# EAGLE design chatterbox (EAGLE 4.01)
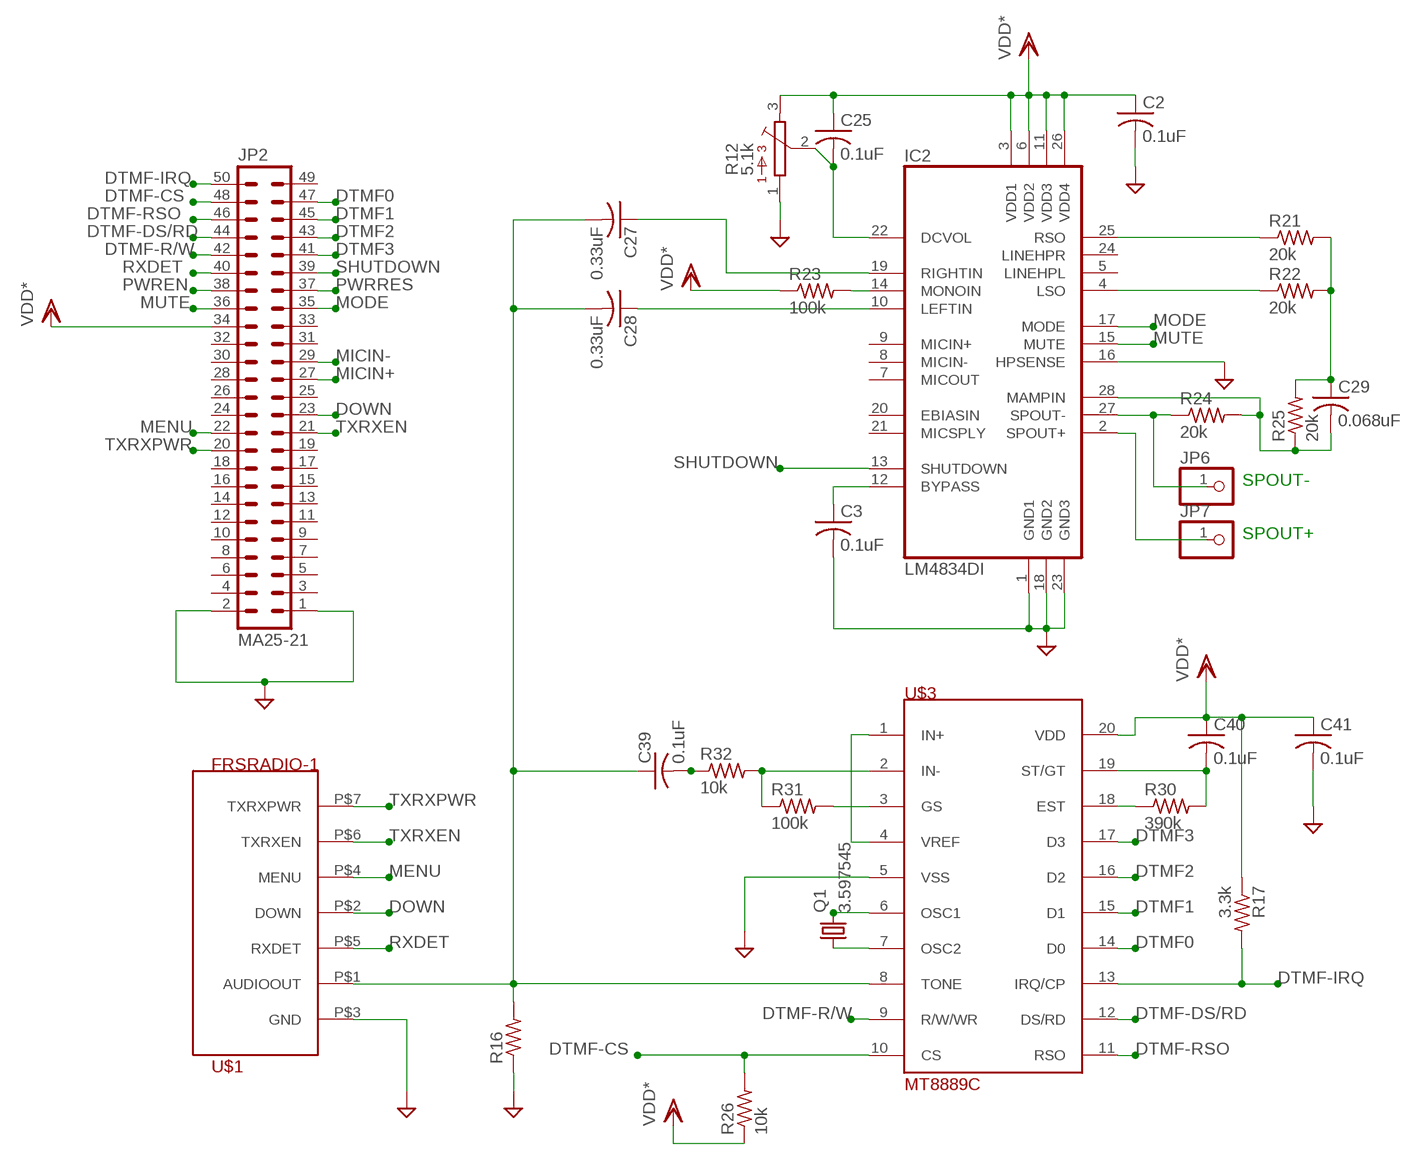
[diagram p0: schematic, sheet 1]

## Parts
C2  0.1uF  C-US050-024X044  [C050-024X044]
C3  0.1uF  C-US050-024X044  [C050-024X044]
C25  0.1uF  C-US050-024X044  [C050-024X044]
C27  0.33uF  C-US050-024X044  [C050-024X044]
C28  0.33uF  C-US050-024X044  [C050-024X044]
C29  0.068uF  C-US050-024X044  [C050-024X044]
C39  0.1uF  C-US050-024X044  [C050-024X044]
C40  0.1uF  C-US050-024X044  [C050-024X044]
C41  0.1uF  C-US050-024X044  [C050-024X044]
IC2  LM4834DI  [DIL28-3]
JP2  MA25-21  [MA25-2]
JP6  PINHD-1X1  [1X01]
JP7  PINHD-1X1  [1X01]
Q1  3.597545  HC49U-V  [HC49U-V]
R12  5.1k  B25U  [B25U]
R16  R-US_0207/10  [0207/10]
R17  3.3k  R-US_0207/10  [0207/10]
R21  20k  R-US_0207/10  [0207/10]
R22  20k  R-US_0207/10  [0207/10]
R23  100k  R-US_0207/10  [0207/10]
R24  20k  R-US_0207/10  [0207/10]
R25  20k  R-US_0207/10  [0207/10]
R26  10k  R-US_0207/10  [0207/10]
R30  390k  R-US_0207/10  [0207/10]
R31  100k  R-US_0207/10  [0207/10]
R32  10k  R-US_0207/10  [0207/10]
U$1  FRSRADIO-1  [FRSRADIO]
U$3  MT8889C  [DIL20]

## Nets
AUDIOIN: C27.2 C39.1 R16.2 U$1.P$1(AUDIOOUT) U$3.8(TONE)
DOWN: JP2.23 U$1.P$2(DOWN)
DTMF0: JP2.47 U$3.14(D0)
DTMF1: JP2.45 U$3.15(D1)
DTMF2: JP2.43 U$3.16(D2)
DTMF3: JP2.41 U$3.17(D3)
DTMF-CS: JP2.48 R26.2 U$3.10(CS)
DTMF-DS/RD: JP2.44 U$3.12(DS/RD)
DTMF-IRQ: JP2.50 R17.2 U$3.13(IRQ/CP)
DTMF-R/W: JP2.42 U$3.9(R/W/WR)
DTMF-RSO: JP2.46 U$3.11(RSO)
GND: C2.2 C3.2 C41.2 IC2.1(GND1) IC2.16(HPSENSE) IC2.18(GND2) IC2.23(GND3) JP2.1 JP2.2 R12.1 R16.1 U$1.P$3(GND) U$3.5(VSS)
MENU: JP2.22 U$1.P$4(MENU)
MICIN+: JP2.27
MICIN-: JP2.29
MODE: IC2.17(MODE) JP2.35
MUTE: IC2.15(MUTE) JP2.36
N$1: C28.2
N$6: IC2.27(SPOUT-) JP6.1 R24.1
N$9: IC2.2(SPOUT+) JP7.1
N$14: C29.2 IC2.28(MAMPIN) R24.2 R25.1
N$18: C3.1 IC2.12(BYPASS)
N$20: C25.2 IC2.22(DCVOL) R12.2
N$29: U$3.1(IN+) U$3.4(VREF)
N$30: R30.1 U$3.18(EST)
N$32: Q1.1 U$3.7(OSC2)
N$33: R31.2 U$3.3(GS)
N$36: C39.2 R32.1
N$37: IC2.14(MONOIN) R23.2
N$38: R31.1 R32.2 U$3.2(IN-)
N$41: C40.2 R30.2 U$3.19(ST/GT)
N$42: IC2.25(RSO) R21.1
N$44: Q1.2 U$3.6(OSC1)
N$45: IC2.4(LSO) R22.1
N$46: C29.1 R21.2 R22.2 R25.2
N$51: C27.1 IC2.19(RIGHTIN)
N$54: C28.1 IC2.10(LEFTIN)
PWREN: JP2.38
PWRRES: JP2.37
RXDET: JP2.40 U$1.P$5(RXDET)
SHUTDOWN: IC2.13(SHUTDOWN) JP2.39
TXRXEN: JP2.21 U$1.P$6(TXRXEN)
TXRXPWR: JP2.20 U$1.P$7(TXRXPWR)
VDD: C2.1 C25.1 C40.1 C41.1 IC2.3(VDD1) IC2.6(VDD2) IC2.11(VDD3) IC2.26(VDD4) JP2.34 R12.3 R17.1 R23.1 R26.1 U$3.20(VDD) ; supply symbol labelled VDD*
Unconnected: IC2.5(LINEHPL) IC2.7(MICOUT) IC2.8(MICIN-) IC2.9(MICIN+) IC2.20(EBIASIN) IC2.21(MICSPLY) IC2.24(LINEHPR) JP2.3 JP2.4 JP2.5 JP2.6 JP2.7 JP2.8 JP2.9 JP2.10 JP2.11 JP2.12 JP2.13 JP2.14 JP2.15 JP2.16 JP2.17 JP2.18 JP2.19 JP2.24 JP2.25 JP2.26 JP2.28 JP2.30 JP2.31 JP2.32 JP2.33 JP2.49

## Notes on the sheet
- SPOUT-
- SPOUT+

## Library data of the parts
C2 C3 C25 C27-C29 C39-C41 = rcl:C-US: CAPACITOR, American symbol
IC2 = chatterbox:LM4834: 1.75W Audio Power Amplifier with DC Volume Control and Microphone Preamp
JP2 = chatterbox:MA25-2
JP6 JP7 = pinhead:PINHD-1X1: PIN HEADER
Q1 = crystal:HC49U-V: CRYSTAL
R12 = pot:B25U: POTENTIOMETER
R16 R17 R21-R26 R30-R32 = rcl:R-US_: RESISTOR, American symbol
U$1 = chatterbox:FRSRADIO
U$3 = chatterbox:MT8889

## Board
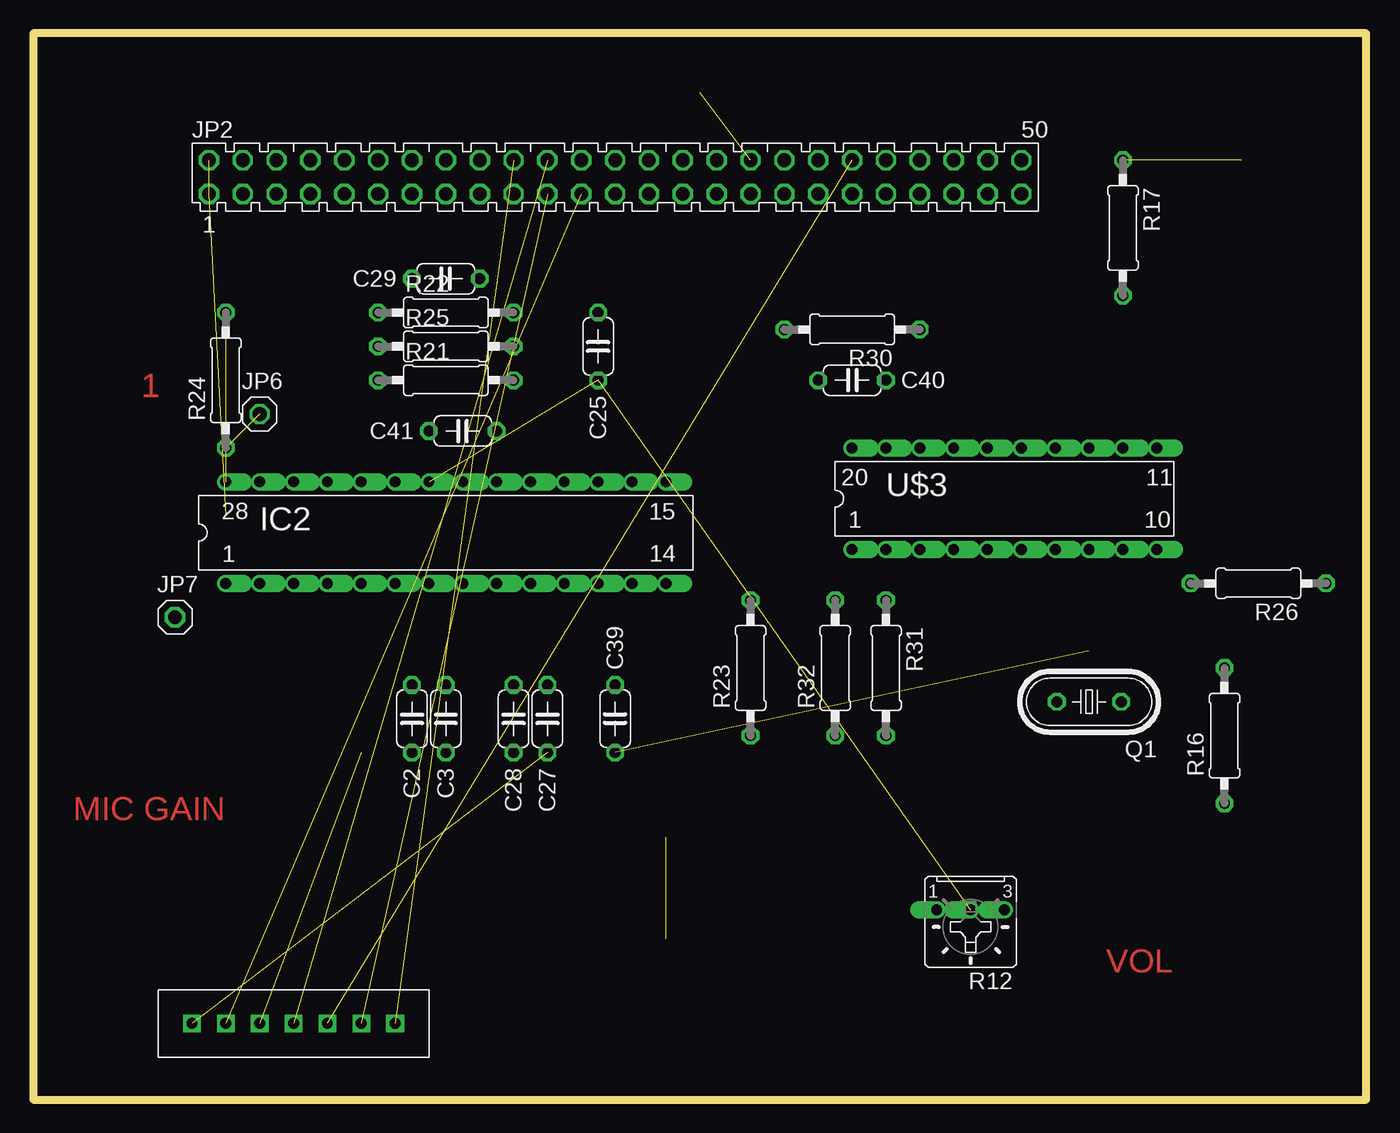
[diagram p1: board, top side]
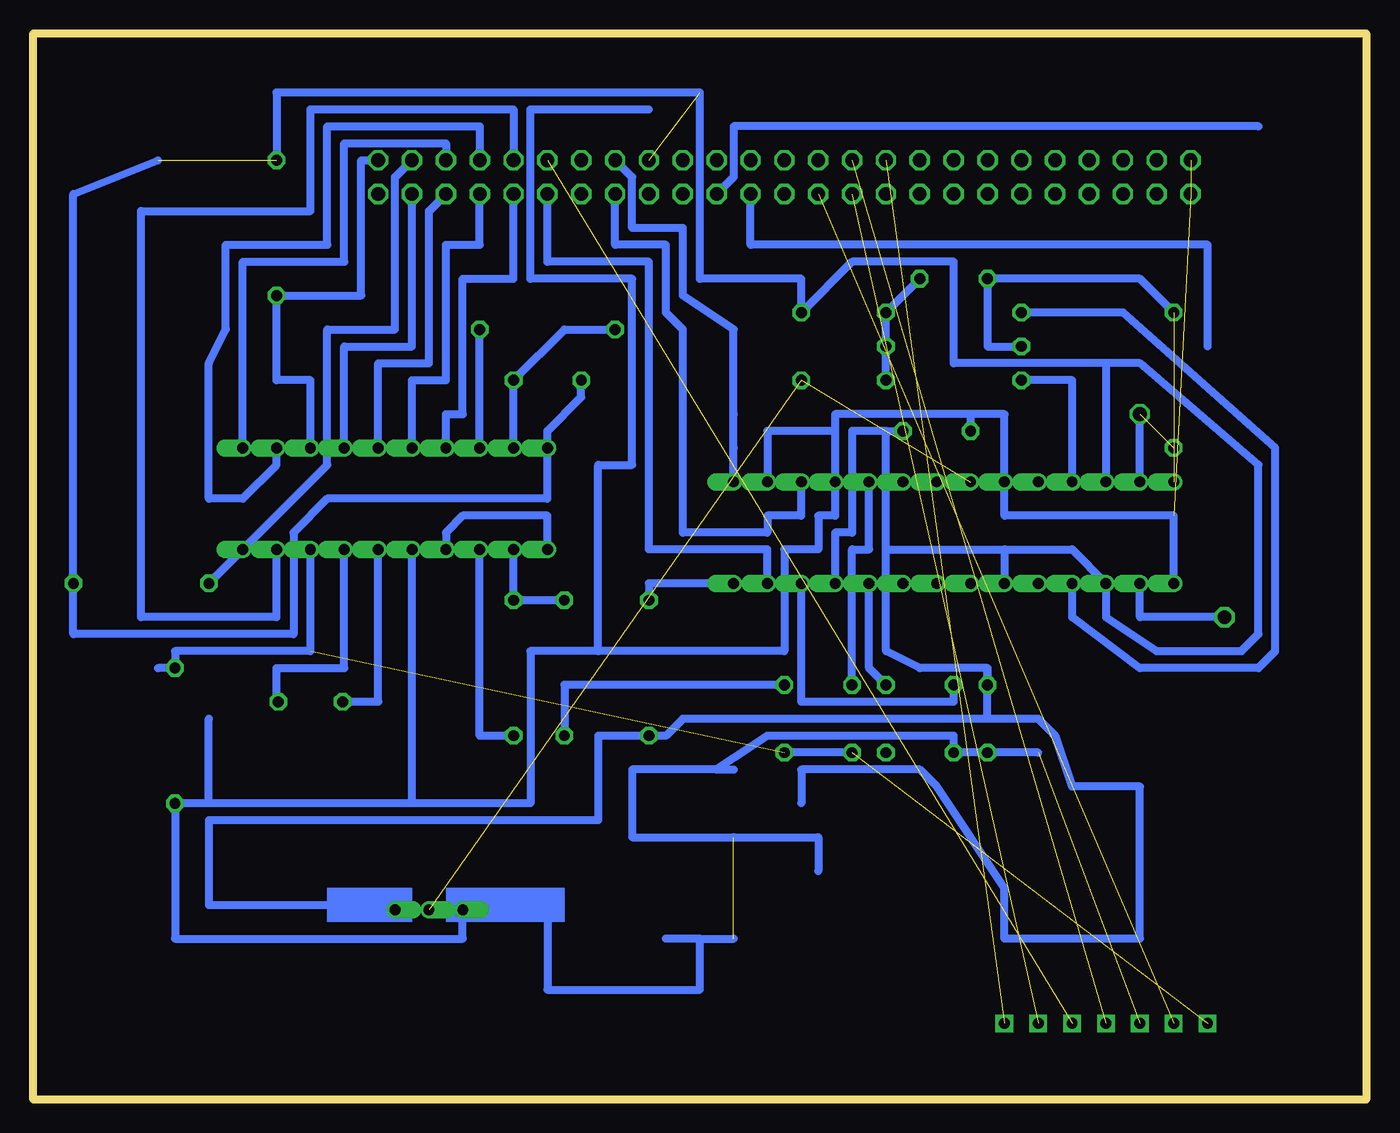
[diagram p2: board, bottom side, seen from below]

Size 100 x 80 mm. Coordinates in mm from the lower left corner, seen from the top.
Outline: 0,0 100,0 100,80 0,80 0,0
Copper layers used: Bottom

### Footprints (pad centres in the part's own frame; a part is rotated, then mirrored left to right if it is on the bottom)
C050-024X044 = drill 0.813 octagon: 1 -2.54,0; 2 2.54,0
DIL28-3 = drill 0.813 offset: 1 -16.51,-3.81; 2 -13.97,-3.81; 3 -11.43,-3.81; 4 -8.89,-3.81; 5 -6.35,-3.81; 6 -3.81,-3.81; 7 -1.27,-3.81; 8 1.27,-3.81; 9 3.81,-3.81; 10 6.35,-3.81; 11 8.89,-3.81; 12 11.43,-3.81; 13 13.97,-3.81; 14 16.51,-3.81; 15 16.51,3.81; 16 13.97,3.81; 17 11.43,3.81; 18 8.89,3.81; 19 6.35,3.81; 20 3.81,3.81; 21 1.27,3.81; 22 -1.27,3.81; 23 -3.81,3.81; 24 -6.35,3.81; 25 -8.89,3.81; 26 -11.43,3.81; 27 -13.97,3.81; 28 -16.51,3.81
MA25-2 = drill 1.016 octagon: 1 -24.13,-1.27; 2 -24.13,1.27; 3 -21.59,-1.27; 4 -21.59,1.27; 5 -19.05,-1.27; 6 -19.05,1.27; 7 -16.51,-1.27; 8 -16.51,1.27; 9 -13.97,-1.27; 10 -13.97,1.27; 11 -11.43,-1.27; 12 -11.43,1.27; 13 -8.89,-1.27; 14 -8.89,1.27; 15 -6.35,-1.27; 16 -6.35,1.27; 17 -3.81,-1.27; 18 -3.81,1.27; 19 -1.27,-1.27; 20 -1.27,1.27; 21 1.27,-1.27; 22 1.27,1.27; 23 3.81,-1.27; 24 3.81,1.27; 25 6.35,-1.27; 26 6.35,1.27; 27 8.89,-1.27; 28 8.89,1.27; 29 11.43,-1.27; 30 11.43,1.27; 31 13.97,-1.27; 32 13.97,1.27; 33 16.51,-1.27; 34 16.51,1.27; 35 19.05,-1.27; 36 19.05,1.27; 37 21.59,-1.27; 38 21.59,1.27; 39 24.13,-1.27; 40 24.13,1.27; 41 26.67,-1.27; 42 26.67,1.27; 43 29.21,-1.27; 44 29.21,1.27; 45 31.75,-1.27; 46 31.75,1.27; 47 34.29,-1.27; 48 34.29,1.27; 49 36.83,-1.27; 50 36.83,1.27
1X01 = drill 1.016 octagon: 1 0,0
HC49U-V = drill 0.813 octagon: 1 -2.413,0; 2 2.413,0
B25U = drill 0.813 offset: 1 2.54,-0.889; 2 0,-0.889; 3 -2.54,-0.889
0207/10 = drill 0.813 octagon: 1 -5.08,0; 2 5.08,0
FRSRADIO = drill 0.813 square: P$1 -7.62,0; P$2 -5.08,0; P$3 -2.54,0; P$4 0,0; P$5 2.54,0; P$6 5.08,0; P$7 7.62,0
DIL20 = drill 0.813 offset: 1 -11.43,-3.81; 2 -8.89,-3.81; 3 -6.35,-3.81; 4 -3.81,-3.81; 5 -1.27,-3.81; 6 1.27,-3.81; 7 3.81,-3.81; 8 6.35,-3.81; 9 8.89,-3.81; 10 11.43,-3.81; 11 11.43,3.81; 12 8.89,3.81; 13 6.35,3.81; 14 3.81,3.81; 15 1.27,3.81; 16 -1.27,3.81; 17 -3.81,3.81; 18 -6.35,3.81; 19 -8.89,3.81; 20 -11.43,3.81

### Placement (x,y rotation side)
C2  28.41,28.57 270 top
C3  30.95,28.57 270 top
C25  42.38,56.51 270 top
C27  38.57,28.57 270 top
C28  36.03,28.57 270 top
C29  30.95,61.59 180 top
C39  43.65,28.57 90 top
C40  61.43,53.97 0 top
C41  32.22,50.16 180 top
IC2  30.95,42.54 0 top
JP2  37.3,69.21 0 top
JP6  16.98,51.43 0 top
JP7  10.63,36.19 0 top
Q1  79.21,29.84 180 top
R12  70.32,13.33 180 top
R16  89.37,27.3 90 top
R17  81.75,65.4 270 top
R21  30.95,53.97 0 top
R22  30.95,59.05 0 top
R23  53.81,32.38 90 top
R24  14.44,53.97 90 top
R25  30.95,56.51 0 top
R26  91.91,38.73 180 top
R30  61.43,57.78 180 top
R31  63.97,32.38 270 top
R32  60.16,32.38 90 top
U$1  19.52,5.71 0 top
U$3  72.86,45.08 0 top

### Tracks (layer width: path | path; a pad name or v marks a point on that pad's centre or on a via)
AUDIOIN  (2 unrouted)
  Bottom 0.61: C27.2 C39.1 | 90.64,32.38 R16.2 89.37,33.65 79.21,33.65 U$3.8
DOWN  (1 unrouted)
DTMF0
  Bottom 0.61: JP2.47 71.59,56.51 76.67,56.51 U$3.14
DTMF1
  Bottom 0.61: JP2.45 70.32,66.67 70.32,55.24 74.13,55.24 U$3.15
DTMF2
  Bottom 0.61: JP2.43 66.51,64.13 69.05,64.13 69.05,53.97 71.59,53.97 U$3.16
DTMF3
  Bottom 0.61: JP2.41 63.97,61.59 67.78,61.59 67.78,51.43 69.05,51.43 U$3.17
DTMF-CS
  Bottom 0.61: R26.2 U$3.10 77.94,47.62 77.94,57.78 72.86,57.78 72.86,69.21 JP2.48
DTMF-DS/RD
  Bottom 0.61: U$3.12 81.75,47.62 84.29,45.08 86.83,45.08 86.83,55.24 85.56,57.78 85.56,64.13 77.94,64.13 77.94,73.02 66.51,73.02 JP2.44
DTMF-IRQ
  Bottom 0.61: U$3.13 79.21,53.97 81.75,53.97 R17.2 75.4,60.32 75.4,70.48 JP2.50
DTMF-R/W
  Bottom 0.61: U$3.9 81.75,36.19 91.91,36.19 91.91,66.67 79.21,66.67 79.21,74.29 63.97,74.29 JP2.42
DTMF-RSO
  Bottom 0.61: JP2.46 69.05,71.75 76.67,71.75 76.67,62.86 84.29,62.86 U$3.11
GND  (4 unrouted)
  Bottom 0.61: 50,12.06 47.46,12.06 | 50,12.06 52.54,12.06 | 50,12.06 50,8.25 61.43,8.25 61.43,14.6 67.78,14.6 R12.1 67.78,12.06 89.37,12.06 R16.1 86.83,22.22 | 41.11,17.14 41.11,19.68 47.46,19.68 55.08,19.68 55.08,24.76 48.73,24.76 | 48.73,24.76 47.46,24.76 | IC2.1 14.44,43.81 27.14,43.81 IC2.23 27.14,51.43 29.68,51.43 | 71.59,22.22 U$3.5 | 71.59,22.22 86.83,22.22 | 86.83,22.22 86.83,28.57 | 57.62,33.65 62.7,33.65 62.7,22.22 71.59,22.22 | 57.62,33.65 43.65,33.65 43.65,41.27 41.11,41.27 41.11,43.81 39.84,43.81 IC2.18 39.84,50.16 | 29.68,51.43 39.84,51.43 39.84,50.16 | 39.84,50.16 44.92,50.16 IC2.16 | 29.68,51.43 C41.2 | 53.81,74.29 62.7,74.29 62.7,61.59 55.08,61.59 55.08,47.62 57.62,47.62 57.62,33.65 | 48.73,24.76 44.92,27.3 30.95,27.3 C3.2 C2.2 24.6,26.03
MENU  (1 unrouted)
MICIN+
  Bottom 0.61: 11.9,56.51 11.9,64.13 46.19,64.13 JP2.27
MICIN-
  Bottom 0.61: JP2.29 47.46,69.21 47.46,73.02 8.09,73.02
MODE
  Bottom 0.61: 51.27,51.43 51.27,42.54 44.92,42.54 44.92,43.81 42.38,43.81 IC2.17 | 51.27,51.43 51.27,52.7 | 51.27,51.43 51.27,57.78 52.54,59.05 52.54,64.13 56.35,64.13 JP2.35
MUTE
  Bottom 0.61: JP2.36 55.08,69.21 55.08,65.4 51.27,65.4 51.27,60.32 47.46,57.78 47.46,48.89 | IC2.15 47.46,48.89 | 47.46,48.89 47.46,51.43
N$6  (1 unrouted)
  Bottom 0.61: IC2.27 JP6.1
N$9
  Bottom 0.61: JP7.1 16.98,36.19 IC2.2
N$14  (1 unrouted)
  Bottom 0.61: R24.2 16.98,61.59 C29.2 28.41,56.51 R25.1
N$18
  Bottom 0.61: C3.1 30.95,29.84 42.38,29.84 IC2.12
N$20  (2 unrouted)
N$29
  Bottom 0.61: U$3.1 61.43,43.81 67.78,43.81 69.05,42.54 U$3.4
N$30
  Bottom 0.61: U$3.18 R30.1
N$32
  Bottom 0.61: Q1.1 81.75,29.84 81.75,32.38 76.67,32.38 U$3.7
N$33
  Bottom 0.61: R31.2 66.51,27.3 U$3.3
N$36
  Bottom 0.61: C39.2 60.16,31.11 R32.1
N$37
  Bottom 0.61: R23.2 53.81,38.73 IC2.14
N$38
  Bottom 0.61: R32.2 R31.1 U$3.2
N$41
  Bottom 0.61: U$3.19 C40.2 60.16,57.78 R30.2
N$42
  Bottom 0.61: R21.1 22.06,53.97 IC2.25
N$44
  Bottom 0.61: Q1.2 74.13,29.84 U$3.6
N$45
  Bottom 0.61: R22.1 18.25,59.05 6.82,48.89 6.82,33.65 8.09,32.38 16.98,32.38 22.06,36.19 IC2.4
N$46
  Bottom 0.61: C29.1 R22.2 R25.2 R21.2
N$51
  Bottom 0.61: C27.1 38.57,41.27 37.3,41.27 IC2.19
N$54
  Bottom 0.61: C28.1 37.3,32.38 IC2.10
RXDET  (1 unrouted)
SHUTDOWN
  Bottom 0.61: IC2.13 44.92,41.27 53.81,41.27 53.81,62.86 61.43,62.86 JP2.39
TXRXEN  (1 unrouted)
TXRXPWR  (1 unrouted)
VDD  (2 unrouted)
  Bottom 0.61: R17.1 81.75,75.56 50,75.56 50,61.59 42.38,61.59 C25.1 38.57,62.86 30.95,62.86 30.95,55.24 19.52,55.24 | C40.1 58.89,52.7 61.43,50.16 U$3.20 61.43,45.08 77.94,45.08 80.48,42.54 80.48,34.92 96.99,34.92 R26.1 96.99,67.94 90.64,70.48 | 28.41,32.38 C2.1 | 28.41,32.38 33.49,32.38 36.03,33.65 36.03,41.27 | 36.03,41.27 36.03,50.16 | 36.03,50.16 C41.1 | 42.38,22.22 42.38,24.76 33.49,24.76 32.22,23.49 27.14,15.87 27.14,12.06 16.98,12.06 16.98,23.49 22.06,23.49 23.33,27.3 24.6,28.57 28.41,28.57 | 28.41,28.57 28.41,32.38 | 28.41,28.57 51.27,28.57 52.54,27.3 R23.1 57.62,27.3 57.62,20.95 86.83,20.95 86.83,14.6 72.86,14.6 R12.3 | 36.03,41.27 27.14,41.27 | 27.14,41.27 22.06,41.27 IC2.3 19.52,36.19 15.71,33.65 9.36,33.65 8.09,34.92 8.09,47.62 16.98,55.24 19.52,55.24 | 27.14,41.27 IC2.6 | 36.03,50.16 38.57,50.16 38.57,42.54 39.84,42.54 IC2.11 | 19.52,55.24 IC2.26
(copper drawn outside any net)
  shapes: Bottom area x2

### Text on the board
Top: 1 | MIC GAIN | VOL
